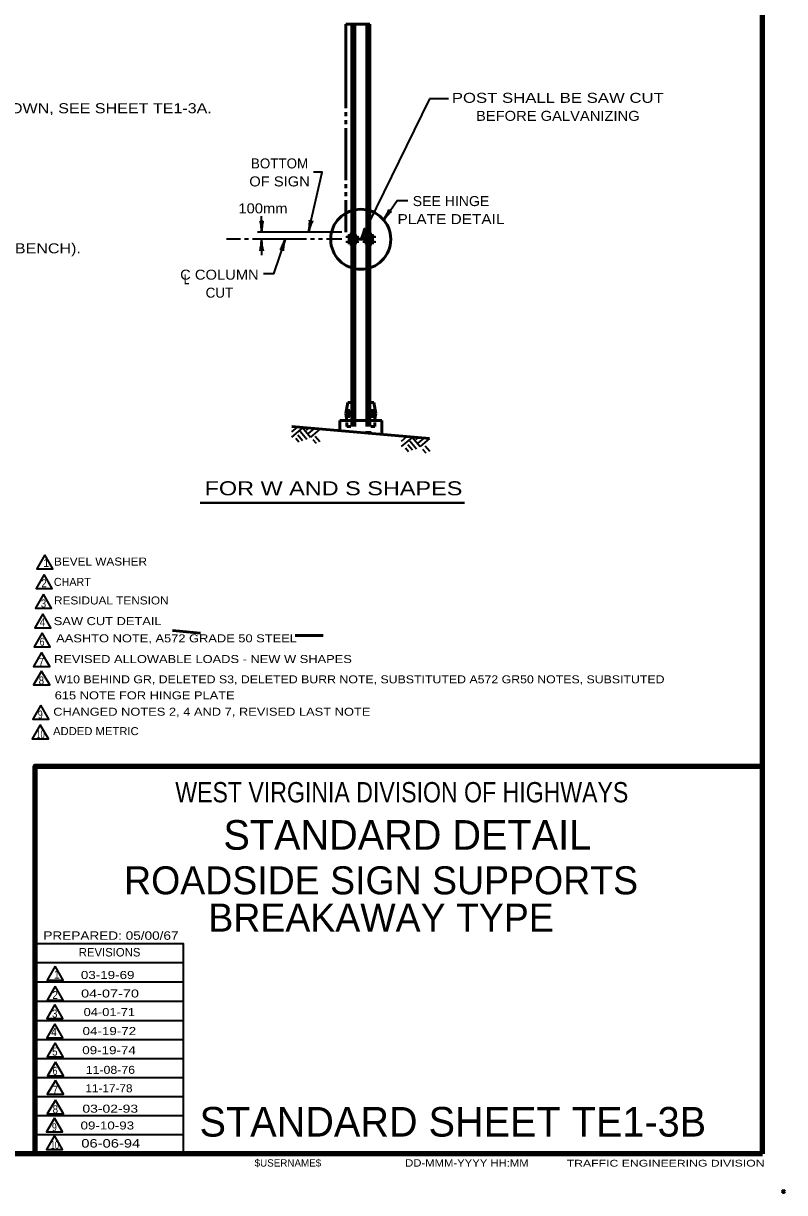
# Model space of a CAD drawing. Extents: x -27 to 686, y -9 to 444.
# Drawn here: x 496 to 686.1, y -9.1 to 283.1 of the extents above; entities that cross this region are included whole.
import ezdxf
from ezdxf.enums import TextEntityAlignment as Align

# ---------------------------------------------------------------- set-up
doc = ezdxf.new("R2010")
doc.units = 0
doc.header["$PDMODE"] = 32
doc.header["$PDSIZE"] = 0.5
doc.linetypes.add('SHORT_DASHED', pattern=[2.7, 1.5, -1.2])
doc.layers.add('1', color=7, linetype='Continuous', lineweight=53)
doc.layers.add('61', color=7, linetype='Continuous', lineweight=35)

msp = doc.modelspace()

# ---------------------------------------------------------------- linework, layer by layer
at = {"layer": '1', "lineweight": 158}
for q in [(680.552, 439.006), (680.552, 97.506), (20.886, 0.589)]:
    msp.add_line((680.552, 0.589), q, dxfattribs=at)
at = {"layer": '1', "lineweight": 13}
msp.add_line((680.552, 0.589), (680.552, 439.006), dxfattribs=at)
at = {"layer": '1'}
for p, q in [((576.456, 282.859), (582.456, 282.859)), ((576.456, 282.859), (576.456, 261.859)), ((577.956, 282.859), (577.956, 183.859)), ((578.706, 282.859), (578.706, 183.859)), ((581.706, 282.859), (581.706, 183.859)), ((582.456, 282.859), (582.456, 183.859)), ((576.456, 260.859), (576.456, 259.859)), ((576.456, 258.859), (576.456, 257.859)), ((576.456, 256.859), (576.456, 243.859)), ((576.456, 242.859), (576.456, 241.859)), ((576.456, 240.859), (576.456, 239.859)), ((576.456, 238.859), (576.456, 230.859)), ((576.956, 229.984), (577.456, 229.984)), ((576.956, 229.984), (576.956, 229.484)), ((576.956, 229.484), (577.456, 229.484)), ((576.956, 228.734), (577.456, 228.734)), ((576.956, 228.734), (576.956, 228.234)), ((576.956, 228.234), (577.456, 228.234)), ((577.456, 230.359), (577.956, 230.359)), ((577.456, 230.359), (577.456, 227.859)), ((579.206, 229.984), (578.706, 229.984)), ((579.206, 229.484), (578.706, 229.484)), ((578.706, 229.109), (581.706, 229.109)), ((579.206, 228.734), (578.706, 228.734)), ((579.206, 228.234), (578.706, 228.234)), ((579.206, 229.984), (579.206, 229.484)), ((579.206, 228.734), (579.206, 228.234)), ((581.706, 229.984), (581.206, 229.984)), ((581.206, 229.984), (581.206, 229.484)), ((581.706, 229.484), (581.206, 229.484)), ((581.206, 228.734), (581.206, 228.234)), ((581.706, 228.734), (581.206, 228.734)), ((581.706, 228.234), (581.206, 228.234)), ((582.456, 230.359), (582.956, 230.359)), ((582.956, 230.359), (582.956, 227.859)), ((582.956, 229.984), (583.456, 229.984)), ((582.956, 229.484), (583.456, 229.484)), ((582.956, 228.734), (583.456, 228.734)), ((582.956, 228.234), (583.456, 228.234)), ((583.456, 229.984), (583.456, 229.484)), ((583.456, 228.734), (583.456, 228.234)), ((577.456, 227.859), (577.956, 227.859)), ((582.456, 227.859), (582.956, 227.859)), ((576.956, 188.359), (576.456, 185.609)), ((576.956, 188.359), (577.956, 188.359)), ((583.456, 188.359), (582.456, 188.359)), ((583.456, 188.359), (583.956, 185.609)), ((576.456, 185.609), (577.956, 185.609)), ((576.774, 183.859), (576.456, 185.609)), ((576.502, 185.859), (577.956, 185.859)), ((576.502, 185.359), (577.956, 185.359)), ((576.979, 185.859), (576.979, 186.359)), ((576.979, 186.359), (577.479, 186.359)), ((576.979, 184.859), (576.979, 185.359)), ((576.979, 184.859), (577.479, 184.859)), ((577.479, 185.859), (577.479, 186.359)), ((577.479, 184.859), (577.479, 185.359)), ((583.911, 185.859), (582.456, 185.859)), ((583.956, 185.609), (582.456, 185.609)), ((583.911, 185.359), (582.456, 185.359)), ((582.934, 185.859), (582.934, 186.359)), ((582.934, 186.359), (583.434, 186.359)), ((582.934, 184.859), (582.934, 185.359)), ((582.934, 184.859), (583.434, 184.859)), ((583.434, 185.859), (583.434, 186.359)), ((583.434, 184.859), (583.434, 185.359)), ((583.638, 183.859), (583.956, 185.609)), ((563.023, 182.36), (597.392, 179.353)), ((574.956, 183.859), (585.456, 183.859)), ((574.956, 183.859), (574.956, 181.316)), ((576.706, 183.359), (576.706, 182.359)), ((576.706, 182.359), (577.706, 182.359)), ((583.706, 182.359), (582.706, 182.359)), ((583.706, 183.359), (583.706, 182.359)), ((585.456, 183.859), (585.456, 180.397)), ((533.248, 131.325), (540.221, 130.714)), ((563.869, 130.102), (570.869, 130.102))]:
    msp.add_line(p, q, dxfattribs=at)
at = {"layer": '1', "lineweight": 35}
for p, q in [((597.372, 264.205), (580.206, 229.109)), ((602.123, 264.205), (597.372, 264.205)), ((555.456, 230.859), (555.456, 234.859)), ((575.456, 230.859), (554.456, 230.859)), ((550.206, 229.109), (546.706, 229.109)), ((552.206, 229.109), (551.206, 229.109)), ((566.706, 229.109), (553.206, 229.109)), ((555.456, 229.109), (555.456, 225.109)), ((568.706, 229.109), (567.706, 229.109)), ((570.706, 229.109), (569.706, 229.109)), ((575.456, 229.109), (571.706, 229.109)), ((576.456, 229.734), (579.706, 229.734)), ((576.456, 228.484), (579.706, 228.484)), ((580.706, 229.734), (583.956, 229.734)), ((580.706, 228.484), (583.956, 228.484)), ((564.334, 182.205), (562.904, 181.005)), ((565.749, 182.081), (562.911, 179.699)), ((565.087, 181.175), (566.78, 179.18)), ((565.649, 182.09), (567.649, 179.706)), ((567.164, 181.957), (566.555, 181.428)), ((568.598, 181.832), (567.103, 180.577)), ((570.013, 181.708), (567.649, 179.706)), ((563.967, 179.386), (564.751, 178.474)), ((564.546, 180.259), (565.709, 178.872)), ((568.276, 179.069), (569.058, 178.138)), ((568.874, 179.94), (570.038, 178.554)), ((591.73, 179.808), (590.3, 178.608)), ((593.144, 179.684), (590.306, 177.302)), ((592.483, 178.778), (594.175, 176.783)), ((593.045, 179.693), (595.045, 177.31)), ((594.559, 179.56), (593.951, 179.031)), ((595.993, 179.435), (594.498, 178.18)), ((597.408, 179.311), (595.045, 177.31)), ((591.363, 176.989), (592.146, 176.077)), ((591.941, 177.862), (593.105, 176.475)), ((595.671, 176.672), (596.453, 175.741)), ((596.27, 177.544), (597.433, 176.157)), ((535.969, 48.339), (498.886, 48.339)), ((535.969, 43.506), (498.886, 43.506)), ((535.969, 38.672), (498.886, 38.672)), ((535.969, 33.839), (498.886, 33.839)), ((535.969, 29.089), (498.886, 29.089)), ((535.969, 24.339), (498.886, 24.339)), ((535.969, 19.589), (498.886, 19.589)), ((535.969, 14.839), (498.886, 14.839)), ((535.969, 10.089), (498.886, 10.089)), ((535.969, 5.339), (498.886, 5.339))]:
    msp.add_line(p, q, dxfattribs=at)
at = {"layer": '1', "linetype": 'SHORT_DASHED'}
for p, q in [((577.956, 183.859), (577.956, 181.053)), ((578.706, 183.859), (578.706, 180.987)), ((581.706, 183.859), (581.706, 180.725)), ((582.456, 183.859), (582.456, 180.659))]:
    msp.add_line(p, q, dxfattribs=at)
at = {"layer": '1', "lineweight": 40}
msp.add_line((540.139, 163.228), (606.163, 163.228), dxfattribs=at)
at = {"layer": '1', "lineweight": 35}
for points in [[(567.179, 230.989), (570.59, 245.901), (568.443, 245.901)], [(585.945, 233.938), (589.288, 238.824), (591.941, 238.824)], [(561.368, 229.093), (558.462, 220.5), (555.936, 220.5)], [(535.969, 0.589), (535.969, 53.089), (498.886, 53.089)]]:
    msp.add_lwpolyline(points, dxfattribs=at)
for points in [[(501.334, 150.251), (499.334, 146.787), (503.334, 146.787)], [(501.176, 145.338), (499.176, 141.874), (503.176, 141.874)], [(501.017, 140.425), (499.017, 136.961), (503.017, 136.961)], [(500.859, 135.513), (498.859, 132.049), (502.859, 132.049)], [(500.701, 130.758), (498.701, 127.294), (502.701, 127.294)], [(500.542, 125.868), (498.542, 122.404), (502.542, 122.404)], [(500.542, 121.217), (498.542, 117.753), (502.542, 117.753)], [(500.346, 112.705), (498.346, 109.241), (502.346, 109.241)], [(500.207, 107.782), (498.207, 104.318), (502.207, 104.318)], [(503.911, 47.474), (501.911, 44.01), (505.911, 44.01)], [(503.899, 42.481), (501.899, 39.017), (505.899, 39.017)], [(503.844, 37.889), (501.844, 34.425), (505.844, 34.425)], [(503.844, 33.059), (501.844, 29.595), (505.844, 29.595)], [(503.876, 28.348), (501.876, 24.884), (505.876, 24.884)], [(503.995, 23.542), (501.995, 20.078), (505.995, 20.078)], [(503.955, 18.95), (501.955, 15.486), (505.955, 15.486)], [(503.955, 14.044), (501.955, 10.58), (505.955, 10.58)], [(503.78, 9.545), (501.78, 6.081), (505.78, 6.081)], [(503.78, 5.186), (501.78, 1.722), (505.78, 1.722)]]:
    msp.add_lwpolyline(points, close=True, dxfattribs=at)
at = {"layer": '1', "lineweight": 158}
msp.add_lwpolyline([(498.886, 0.589), (498.886, 97.506), (680.552, 97.506)], dxfattribs=at)
at = {"layer": '1'}
msp.add_circle((580.206, 229.109), 7.5, dxfattribs=at)
at = {"layer": '1', "lineweight": 40}
for centre, major_axis, ratio, start_param, end_param in [((555.18, 231.951), (0.156, -1.786), 0.122415, 0.8963533, 3.1415927), ((555.18, 231.951), (0.156, -1.786), 0.122415, 0.8963533, 3.1415927), ((555.668, 231.98), (-0.176, -1.756), 0.07063, 3.1407148, 5.41811), ((555.668, 231.98), (-0.176, -1.756), 0.07063, 3.1407148, 5.41811), ((567.153, 232.114), (-0.246, -1.776), 0.122415, 0.8963533, 3.1415927), ((567.635, 232.034), (0.563, 1.673), 0.07063, 6.2823074, 8.5597026), ((586.333, 234.994), (-0.879, -1.562), 0.122415, 0.8963533, 3.1415927), ((586.333, 234.994), (-0.879, -1.562), 0.122415, 0.8963533, 3.1415927), ((586.753, 234.743), (1.137, 1.351), 0.07063, 6.2823074, 8.5597026), ((586.753, 234.743), (1.137, 1.351), 0.07063, 6.2823074, 8.5597026), ((580.437, 230.211), (-0.644, -1.673), 0.122415, 0.8963533, 3.1415927), ((580.889, 230.023), (0.93, 1.501), 0.07063, 6.2823074, 8.5597026), ((555.245, 227.989), (0.176, 1.756), 0.07063, 3.1407148, 5.41811), ((555.733, 228.018), (-0.156, 1.786), 0.122415, 0.8963533, 3.1415927), ((560.809, 228.1), (-0.729, -1.608), 0.07063, 6.2823074, 8.5597026), ((561.28, 227.971), (0.424, 1.742), 0.122415, 0.8963533, 3.1415927)]:
    msp.add_ellipse(centre, major_axis=major_axis, ratio=ratio, start_param=start_param, end_param=end_param, dxfattribs=at)
at = {"layer": '1'}
msp.add_point((685.802, -8.828), dxfattribs=at)
at = {"layer": '61', "lineweight": 53}
for q in [(553.302, 0.589), (553.302, 0.589), (553.302, 0.589), (553.552, 0.589), (553.552, 0.589)]:
    msp.add_line((680.552, 0.589), q, dxfattribs=at)

# ---------------------------------------------------------------- texts
at = {"layer": '1'}
for s, height, width, p in [('FOR BASE CONNECTIONS TO BE USED IN CONJUNCTION WITH THE POLE SELECTION CHART SHOWN, SEE SHEET TE1-3A.', 2.5, 1.2, (302.967, 260.611)), ('CAN BE USED IF THE SUPPORTS ARE LOCATED BEHIND GUARDRAIL (OR ON BENCH).', 2.5, 1.2, (342.723, 225.602)), ('BEVEL WASHER', 2, 1.1, (503.629, 147.599)), ('2', 2, 0.9, (500.47, 142.157)), ('3', 2, 0.9, (500.33, 137.137)), ('RESIDUAL TENSION', 2, 1.1, (503.629, 137.874)), ('4', 2, 0.95, (500.049, 132.432)), ('SAW CUT DETAIL', 2, 1.2, (503.559, 132.713)), ('6', 2, 0.8, (500.049, 127.552)), ('AASHTO NOTE, A572 GRADE 50 STEEL', 2, 1.2, (504.17, 128.413)), ('7', 2, 0.9, (499.803, 122.531)), ('REVISED ALLOWABLE LOADS - NEW W SHAPES', 2, 1.2, (503.629, 123.233)), ('8', 2, 0.9, (499.803, 117.88)), ('W10 BEHIND GR, DELETED S3, DELETED BURR NOTE, SUBSTITUTED A572 GR50 NOTES, SUBSITUTED', 2, 1.15, (503.793, 118.164)), ('615 NOTE FOR HINGE PLATE', 2, 1.2, (503.793, 114.164)), ('9', 2, 0.8, (499.607, 109.368)), ('CHANGED NOTES 2, 4 AND 7, REVISED LAST NOTE', 2, 1.2, (503.433, 110.07)), ('10', 2, 0.7, (499.217, 104.419)), ('ADDED METRIC', 2, 1.05, (503.386, 105.226)), ('PREPARED: 05/00/67', 2.114, 1.2, (500.969, 54.089)), ('2', 2, 0.9, (503.236, 39.294)), ('3', 2, 0.9, (503.125, 34.646)), ('4', 2, 0.95, (502.904, 30.038)), ('5', 2, 0.9, (503.157, 25.161)), ('6', 2, 0.8, (503.276, 20.354)), ('7', 2, 0.9, (503.291, 15.652)), ('8', 2, 0.9, (503.291, 10.746)), ('9', 2, 0.8, (503.117, 6.247)), ('10', 2, 0.7, (502.79, 1.823)), ('DD-MMM-YYYY HH:MM', 1.833, 1.15, (591.302, -2.578)), ('TRAFFIC ENGINEERING DIVISION', 1.693, 1.35, (631.636, -2.578))]:
    msp.add_text(s, height=height, dxfattribs=dict(at, width=width)).set_placement(p)
for s, height, width, p in [('POST SHALL BE SAW CUT', 2.5, 1.25, (629.424, 263.202)), ('BEFORE GALVANIZING', 2.5, 1.1, (629.424, 258.702)), ('OF SIGN', 2.5, 1.1, (559.943, 242.321)), ('SEE HINGE', 2.5, 1.05, (602.751, 237.404)), ('100mm', 2.5, 1.1, (555.797, 235.59)), ('PLATE DETAIL', 2.5, 1.15, (602.751, 232.904)), ('C COLUMN', 2.5, 1.1, (544.927, 219.02)), ('L', 2.5, 0.75, (536.746, 217.891)), ('FOR W AND S SHAPES', 3.5, 1.25, (573.405, 165.151)), ('WEST VIRGINIA DIVISION OF HIGHWAYS', 5.074, 0.85, (590.469, 88.422)), ('03-19-69', 2, 1.25, (517.024, 44.301)), ('04-07-70', 2, 1.35, (517.61, 39.672)), ('04-01-71', 2, 1.2, (517.443, 35.034)), ('04-19-72', 2, 1.25, (517.443, 30.286)), ('09-19-74', 2, 1.25, (517.37, 25.511)), ('11-08-76', 2, 1.15, (517.705, 20.595)), ('11-17-78', 2, 1.1, (517.343, 15.995)), ('03-02-93', 2, 1.3, (517.666, 10.893)), ('09-10-93', 2, 1.25, (516.938, 6.698)), ('06-06-94', 2.116, 1.3, (517.794, 2.176))]:
    msp.add_text(s, height=height, dxfattribs=dict(at, width=width)).set_placement(p, align=Align.CENTER)
for s, height, p in [('BOTTOM', 2.5, (559.943, 246.821)), ('CUT', 2.5, (544.927, 214.52)), ('STANDARD DETAIL', 7.401, (591.844, 76.589)), ('ROADSIDE SIGN SUPPORTS', 6.993, (585.293, 65.45)), ('BREAKAWAY TYPE', 6.993, (585.293, 56.134))]:
    msp.add_text(s, height=height, dxfattribs=at).set_placement(p, align=Align.CENTER)
for s, height, p in [('1', 2, (500.962, 147.248)), ('CHART', 2, (503.594, 142.508)), ('REVISIONS', 2.114, (509.802, 49.922)), ('1', 2, (503.579, 44.397)), ('STANDARD SHEET TE1-3B', 7.401, (539.969, 4.922)), ('$USERNAME$', 1.833, (553.719, -2.578))]:
    msp.add_text(s, height=height, dxfattribs=at).set_placement(p)

doc.saveas('drawing.dxf')
